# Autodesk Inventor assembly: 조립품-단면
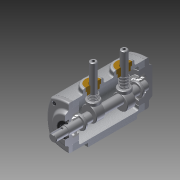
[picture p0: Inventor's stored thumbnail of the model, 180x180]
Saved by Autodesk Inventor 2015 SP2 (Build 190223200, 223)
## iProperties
Created: 2015-06
Part Number: 조립품-단면
Document SubType Name: Assembly
Designer: AMC
Author: AMC
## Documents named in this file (12)
- C:\Users\AMC\Desktop\350620V1008\조립품-단면.iam
- C:\Users\AMC\Desktop\350620V1008\M4-소켓머리.ipt
- C:\Users\AMC\Desktop\350620V1008\뒷커버 - 복사본.ipt
- C:\Users\AMC\Desktop\350620V1008\베어링 6203 - 복사본.ipt
- C:\Users\AMC\Desktop\350620V1008\본체 - 복사본.ipt
- C:\Users\AMC\Desktop\350620V1008\부시 - 복사본.ipt
- C:\Users\AMC\Desktop\350620V1008\스프링10.ipt
- C:\Users\AMC\Desktop\350620V1008\스프링11.ipt
- C:\Users\AMC\Desktop\350620V1008\슬라이더.ipt
- C:\Users\AMC\Desktop\350620V1008\앞커버 - 복사본.ipt
- C:\Users\AMC\Desktop\350620V1008\오일실 - 복사본.ipt
- C:\Users\AMC\Desktop\350620V1008\축.ipt
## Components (7 placed, 3 different names)
1. 9-M4-소켓머리:1
2. 7-베어링 6203:1 — 플러쉬:2
3. 8-오일실:1 — 플러쉬:7
4. 7-베어링 6203:2 — 플러쉬:6
5. 9-M4-소켓머리:2
6. 9-M4-소켓머리:3
7. 9-M4-소켓머리:5
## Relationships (3: Flush 3)
- 플러쉬:2 [Flush]: 7-베어링 6203:1
- 플러쉬:6 [Flush]: 7-베어링 6203:2
- 플러쉬:7 [Flush]: 8-오일실:1
